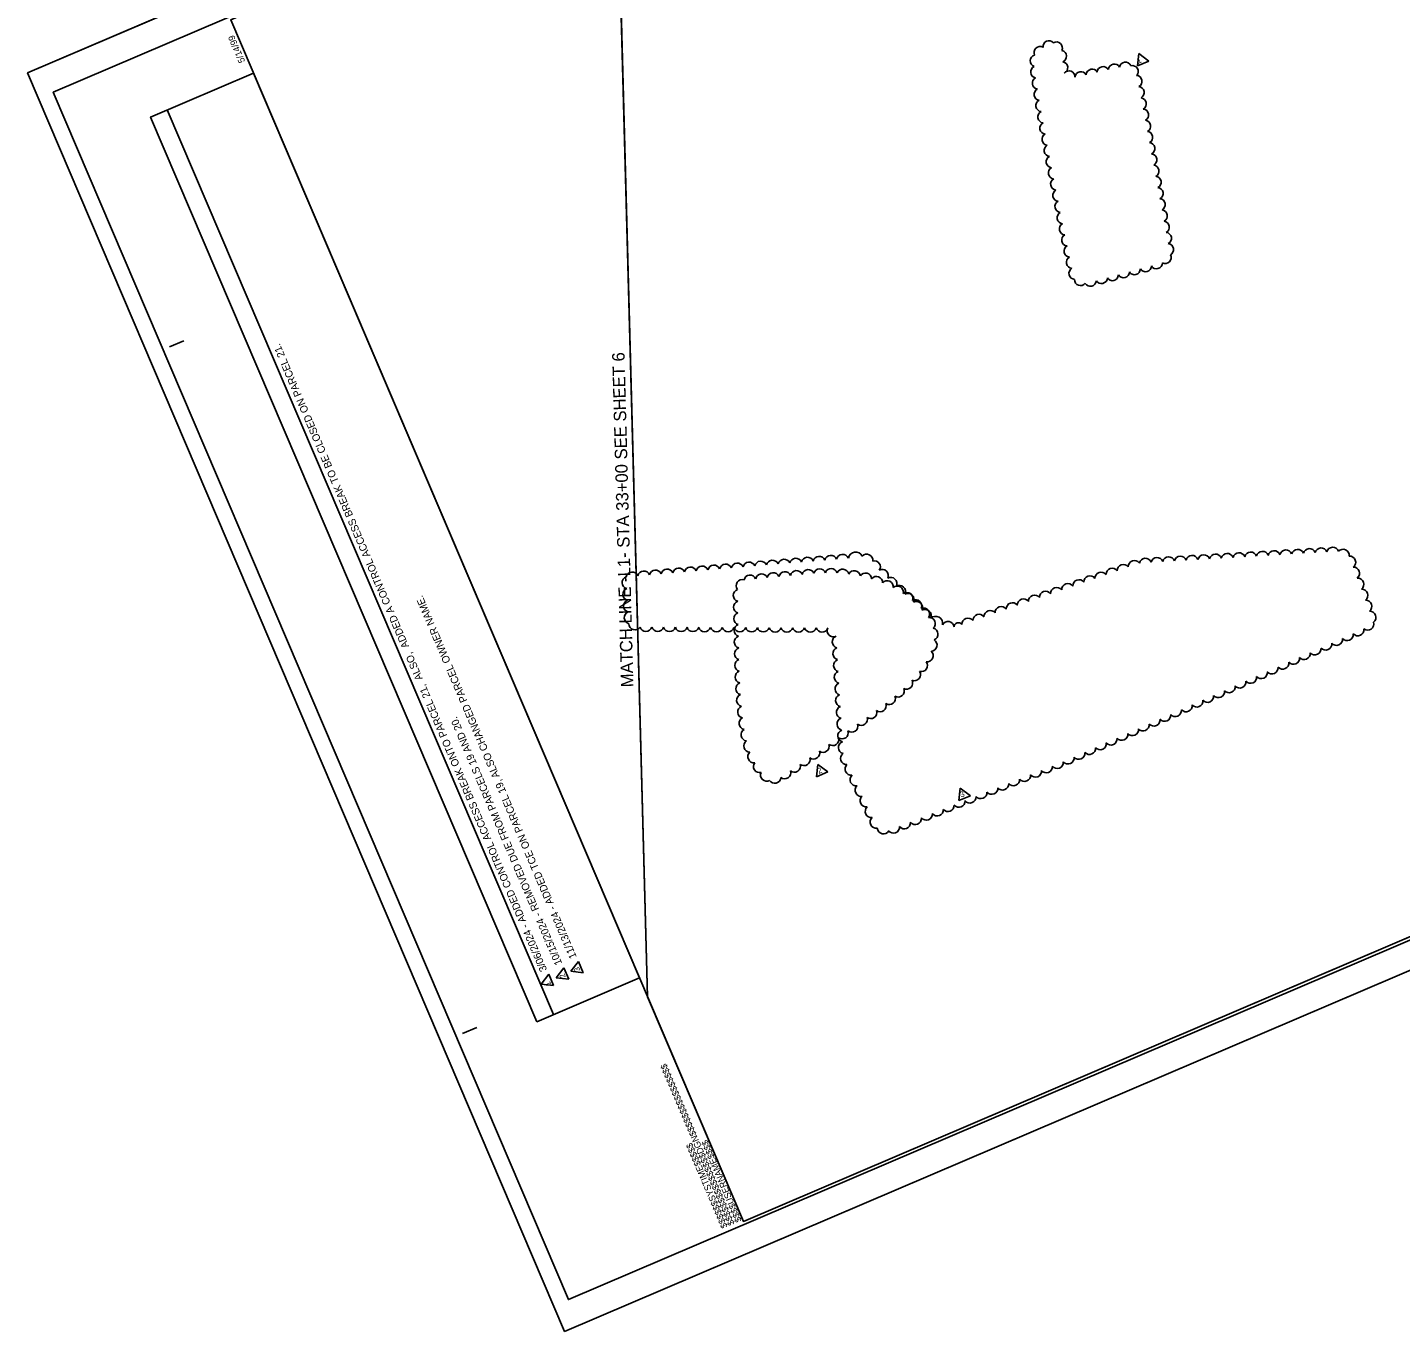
# Model space of a CAD drawing. Extents: x 2192740 to 2194721, y 86011 to 87688.
# Drawn here: x 2192740 to 2193845, y 86011 to 87060 of the extents above; entities that cross this region are included whole.
import ezdxf

# ---------------------------------------------------------------- set-up
doc = ezdxf.new("R2010")
doc.units = 0
for name, color, linetype in [('CTL Primary Horizontal Cogo Comment', 7, 'Continuous'), ('CTL Primary Horizontal Cogo Elevation', 7, 'Continuous'), ('CTL Primary Horizontal Cogo Number', 7, 'Continuous'), ('Exist Other Culture Sign', 7, 'Continuous'), ('Exist Property Iron Pin Cogo Comment', 7, 'Continuous'), ('Exist Utilities Other Traffic Signal Box CELL', 7, 'Continuous'), ('Old_Level_6', 7, 'Continuous')]:
    doc.layers.add(name, color=color, linetype=linetype)

msp = doc.modelspace()

# ---------------------------------------------------------------- linework, layer by layer
at = {"layer": 'CTL Primary Horizontal Cogo Comment'}
for p, q in [((2194289.2, 87684.3), (2192740.5, 87023)), ((2192740.5, 87023), (2193172.4, 86011.4)), ((2193172.4, 86011.4), (2194721.1, 86672.6))]:
    msp.add_line(p, q, dxfattribs=at)
at = {"layer": 'CTL Primary Horizontal Cogo Elevation'}
msp.add_lwpolyline([(2194289.2, 87684.3), (2192740.5, 87023), (2193172.4, 86011.4), (2194721.1, 86672.6)], close=True, dxfattribs=at)
at = {"layer": 'CTL Primary Horizontal Cogo Number'}
msp.add_lwpolyline([(2194293.9, 87661.9), (2192761.2, 87007.5), (2193175.5, 86037.1), (2194708.2, 86691.5)], close=True, dxfattribs=at)
at = {"layer": 'Exist Other Culture Sign'}
for p, q in [((2192854.6, 86802.7), (2192866.1, 86807.6)), ((2193090.2, 86250.8), (2193101.7, 86255.8))]:
    msp.add_line(p, q, dxfattribs=at)
msp.add_lwpolyline([(2194283.4, 87654.6), (2192903.9, 87065.6), (2193316.2, 86099.9), (2194695.7, 86688.9)], close=True, dxfattribs=at)
at = {"layer": 'Exist Property Iron Pin Cogo Comment'}
msp.add_line((2193214.5, 87198.2), (2193239.1, 86280.3), dxfattribs=at)
at = {"layer": 'Exist Utilities Other Traffic Signal Box CELL'}
msp.add_lwpolyline([(2194135.7, 87491), (2194167.5, 87416.4), (2194338.2, 87489.3), (2194682.4, 86683.3), (2193316.2, 86099.9), (2193239.1, 86280.3), (2193214.5, 87198.2), (2193975.8, 87523.3), (2194012.1, 87438.3)], close=True, dxfattribs=at)
at = {"layer": 'Old_Level_6'}
for p, q in [((2193633.1, 87028.6), (2193634.2, 87038.6)), ((2193633.1, 87028.6), (2193642.3, 87032.5)), ((2193634.2, 87038.6), (2193642.3, 87032.5)), ((2193163.4, 86266.1), (2192852.9, 86993.3)), ((2193374.9, 86457.2), (2193376, 86467.2)), ((2193374.9, 86457.2), (2193384, 86461.1)), ((2193376, 86467.2), (2193384, 86461.1)), ((2193489.5, 86438.1), (2193490.6, 86448.2)), ((2193490.6, 86448.2), (2193498.7, 86442)), ((2193489.5, 86438.1), (2193498.7, 86442)), ((2193165.6, 86295.7), (2193171.8, 86303.7)), ((2193175.7, 86294.6), (2193171.8, 86303.7)), ((2193177.4, 86300.9), (2193183.5, 86308.9)), ((2193187.4, 86299.8), (2193183.5, 86308.9)), ((2193153.6, 86290.6), (2193159.7, 86298.6)), ((2193163.6, 86289.5), (2193159.7, 86298.6)), ((2193175.7, 86294.6), (2193165.6, 86295.7)), ((2193187.4, 86299.8), (2193177.4, 86300.9)), ((2193163.6, 86289.5), (2193153.6, 86290.6))]:
    msp.add_line(p, q, dxfattribs=at)
msp.add_lwpolyline([(2193150, 86260.4), (2192839.5, 86987.5), (2192922.1, 87022.8), (2193232.6, 86295.7)], close=True, dxfattribs=at)
for centre, radius, start, end in [((2193554.7, 87039.4), 4.81, 60.2889, 205.2889), ((2193561.9, 87044), 4.81, 41.2058, 186.2058), ((2193567.9, 87043.1), 4.81, 335.2487, 120.2487), ((2193551.6, 87032.7), 4.81, 104.9388, 249.9388), ((2193571.2, 87036.4), 4.81, 291.3424, 76.3424), ((2193572.2, 87027.2), 4.81, 295.7959, 80.7959), ((2193623.4, 87026.8), 4.81, 24.9884, 169.9884), ((2193552, 87023.8), 4.81, 114.7308, 259.7308), ((2193578, 87019.9), 4.81, 357.2597, 142.2597), ((2193587.6, 87019.2), 4.81, 29.5837, 174.5837), ((2193596.6, 87021.2), 4.81, 30.4862, 175.4862), ((2193605.5, 87023.3), 4.81, 30.7446, 175.7446), ((2193614.5, 87025.3), 4.81, 29.3713, 174.3713), ((2193628.9, 87024.1), 4.81, 318.561, 103.561), ((2193631.9, 87016.2), 4.81, 298.7576, 83.7576), ((2193553.3, 87014.7), 4.81, 116.1613, 261.1613), ((2193554.7, 87005.7), 4.81, 116.8755, 261.8755), ((2193633.7, 87007.2), 4.81, 298.4514, 83.4514), ((2193556.2, 86996.7), 4.81, 117.3247, 262.3247), ((2193635.4, 86998.2), 4.81, 298.3036, 83.3036), ((2193557.8, 86987.6), 4.81, 117.6408, 262.6408), ((2193637.2, 86989.2), 4.81, 298.2119, 83.2119), ((2193559.4, 86978.6), 4.81, 117.879, 262.879), ((2193638.9, 86980.2), 4.81, 298.1478, 83.1478), ((2193640.5, 86971.2), 4.81, 298.0998, 83.0998), ((2193561.1, 86969.6), 4.81, 118.0667, 263.0667), ((2193562.8, 86960.6), 4.81, 118.2196, 263.2196), ((2193642.2, 86962.2), 4.81, 298.0621, 83.0621), ((2193564.5, 86951.6), 4.81, 118.3473, 263.3473), ((2193643.9, 86953.1), 4.81, 298.0314, 83.0314), ((2193566.2, 86942.6), 4.81, 118.4504, 263.4504), ((2193645.6, 86944.1), 4.81, 298.0179, 83.0179), ((2193568, 86933.6), 4.81, 118.5162, 263.5162), ((2193647.3, 86935.1), 4.81, 298.0179, 83.0179), ((2193569.8, 86924.6), 4.81, 118.5875, 263.5875), ((2193648.9, 86926.1), 4.81, 298.0179, 83.0179), ((2193650.6, 86917.1), 4.81, 298.0179, 83.0179), ((2193571.5, 86915.6), 4.81, 118.6737, 263.6737), ((2193573.3, 86906.6), 4.81, 118.781, 263.781), ((2193652.3, 86908.1), 4.81, 298.0179, 83.0179), ((2193575.1, 86897.6), 4.81, 118.9194, 263.9194), ((2193653.9, 86899), 4.81, 298.0179, 83.0179), ((2193576.9, 86888.6), 4.81, 119.108, 264.108), ((2193655.6, 86890), 4.81, 298.0179, 83.0179), ((2193578.8, 86879.7), 4.81, 119.3871, 264.3871), ((2193655.3, 86874.5), 4.81, 243.0878, 28.0878), ((2193657.3, 86881), 4.81, 298.0179, 83.0179), ((2193580.7, 86870.7), 4.81, 119.8662, 264.8662), ((2193582.8, 86861.8), 4.81, 121.0572, 266.0572), ((2193630.6, 86865.6), 4.81, 212.7782, 357.7782), ((2193639.5, 86868), 4.81, 212.7782, 357.7782), ((2193648.3, 86870.4), 4.81, 212.7782, 357.7782), ((2193587.2, 86856.8), 4.8, 177.6331, 322.6331), ((2193595.2, 86856.3), 4.81, 210.4677, 355.4677), ((2193604.1, 86858.5), 4.81, 211.7465, 356.7465), ((2193612.9, 86860.8), 4.81, 212.3611, 357.3611), ((2193621.8, 86863.2), 4.81, 212.7195, 357.7195), ((2193367.7, 86628.8), 4.95, 22.3196, 167.3196), ((2193377.1, 86629.5), 4.95, 22.3196, 167.3196), ((2193386.5, 86630.3), 4.95, 22.3196, 167.3196), ((2193396, 86631.1), 4.95, 22.3196, 167.3196), ((2193406.4, 86632), 5.9, 25.3586, 170.3586), ((2193415.3, 86631.2), 4.95, 352.372, 137.372), ((2193648.8, 86628.5), 4.95, 20.8306, 165.8306), ((2193658.2, 86629.1), 4.95, 20.8306, 165.8306), ((2193667.6, 86629.6), 4.95, 20.8306, 165.8306), ((2193677, 86630.2), 4.95, 20.8306, 165.8306), ((2193686.5, 86630.7), 4.95, 20.8306, 165.8306), ((2193695.9, 86631.3), 4.95, 20.8306, 165.8306), ((2193705.3, 86631.8), 4.95, 20.8306, 165.8306), ((2193714.7, 86632.4), 4.95, 20.8306, 165.8306), ((2193724.2, 86632.9), 4.95, 20.8306, 165.8306), ((2193733.6, 86633.5), 4.95, 20.8306, 165.8306), ((2193743, 86634), 4.95, 20.8306, 165.8306), ((2193752.4, 86634.6), 4.95, 20.8306, 165.8306), ((2193761.9, 86635.1), 4.95, 20.8306, 165.8306), ((2193771.3, 86635.7), 4.95, 20.8306, 165.8306), ((2193780.7, 86636.2), 4.95, 20.8306, 165.8306), ((2193790.1, 86636.8), 4.95, 20.8306, 165.8306), ((2193798.4, 86635.2), 4.95, 353.2616, 138.2616), ((2193803.6, 86629.7), 4.95, 307.6704, 92.6704), ((2193236.1, 86617.7), 4.95, 22.3196, 167.3196), ((2193245.5, 86618.4), 4.95, 22.3196, 167.3196), ((2193254.9, 86619.2), 4.95, 22.3196, 167.3196), ((2193264.3, 86620), 4.95, 22.3196, 167.3196), ((2193273.7, 86620.8), 4.95, 22.3196, 167.3196), ((2193283.1, 86621.6), 4.95, 22.3196, 167.3196), ((2193292.5, 86622.4), 4.95, 22.3196, 167.3196), ((2193301.9, 86623.2), 4.95, 22.3196, 167.3196), ((2193311.3, 86624), 4.95, 22.3196, 167.3196), ((2193320.7, 86624.8), 4.95, 22.3196, 167.3196), ((2193330.1, 86625.6), 4.95, 22.3196, 167.3196), ((2193339.5, 86626.4), 4.95, 22.3196, 167.3196), ((2193348.9, 86627.2), 4.95, 22.3196, 167.3196), ((2193349.6, 86617.2), 4.92, 22.9559, 167.9559), ((2193358.3, 86628), 4.95, 22.3196, 167.3196), ((2193358.9, 86618.1), 4.92, 22.9559, 167.9559), ((2193368.3, 86618.9), 4.92, 22.63, 167.63), ((2193377.6, 86619.5), 4.92, 19.9186, 164.9186), ((2193386.8, 86619.7), 4.92, 16.408, 161.408), ((2193396.1, 86619.2), 4.92, 12.4747, 157.4747), ((2193405.3, 86618), 4.92, 8.0943, 153.0943), ((2193421.7, 86626.1), 4.64, 323.0557, 108.0557), ((2193427.8, 86619), 4.95, 334.3989, 119.3989), ((2193612.8, 86619.9), 4.95, 36.5816, 181.5816), ((2193621.7, 86623), 4.95, 36.5816, 181.5816), ((2193630.6, 86626.1), 4.95, 36.5816, 181.5816), ((2193639.4, 86627.9), 4.95, 21.8357, 166.8357), ((2193806.8, 86620.9), 4.95, 307.6704, 92.6704), ((2193223.6, 86613.3), 4.95, 110.9039, 255.9039), ((2193226.7, 86616.9), 4.95, 22.3196, 167.3196), ((2193315.3, 86610.8), 4.92, 73.4623, 218.4623), ((2193321.5, 86614.5), 4.92, 22.9559, 167.9559), ((2193330.9, 86615.4), 4.92, 22.9559, 167.9559), ((2193340.2, 86616.3), 4.92, 22.9559, 167.9559), ((2193414.4, 86616.1), 4.92, 3.2672, 148.2672), ((2193423.2, 86613.4), 4.92, 358.0319, 143.0319), ((2193431.8, 86609.9), 4.92, 352.4751, 137.4751), ((2193434.7, 86612.6), 4.95, 334.3989, 119.3989), ((2193441.6, 86606.1), 4.95, 334.3989, 119.3989), ((2193577.1, 86607.6), 4.95, 36.5816, 181.5816), ((2193586, 86610.7), 4.95, 36.5816, 181.5816), ((2193594.9, 86613.8), 4.95, 36.5816, 181.5816), ((2193603.8, 86616.8), 4.95, 36.5816, 181.5816), ((2193810.1, 86612), 4.95, 307.6704, 92.6704), ((2193224.2, 86603.9), 4.95, 110.9039, 255.9039), ((2193313, 86603.1), 4.92, 108.6436, 253.6436), ((2193439.9, 86605.6), 4.92, 346.7306, 131.7306), ((2193447.6, 86600.5), 4.92, 340.9648, 125.9648), ((2193448.5, 86599.7), 4.95, 334.3989, 119.3989), ((2193541.4, 86595.2), 4.95, 36.5816, 181.5816), ((2193550.3, 86598.3), 4.95, 36.5816, 181.5816), ((2193559.2, 86601.4), 4.95, 36.5816, 181.5816), ((2193568.1, 86604.5), 4.95, 36.5816, 181.5816), ((2193813.4, 86603.1), 4.95, 307.6704, 92.6704), ((2193224.7, 86594.5), 4.95, 110.9039, 255.9039), ((2193225.3, 86585.1), 4.95, 110.9039, 255.9039), ((2193313.2, 86593.7), 4.92, 108.6436, 253.6436), ((2193313.4, 86584.3), 4.92, 108.6436, 253.6436), ((2193454.7, 86594.6), 4.92, 335.3457, 120.3457), ((2193455.4, 86593.2), 4.95, 334.3989, 119.3989), ((2193461, 86588), 4.92, 326.3341, 111.3341), ((2193462.3, 86586.8), 4.95, 334.3989, 119.3989), ((2193514.6, 86586), 4.95, 36.5816, 181.5816), ((2193523.5, 86589.1), 4.95, 36.5816, 181.5816), ((2193532.5, 86592.2), 4.95, 36.5816, 181.5816), ((2193816.6, 86594.3), 4.95, 307.6704, 92.6704), ((2193819.9, 86585.4), 4.95, 307.6704, 92.6704), ((2193229, 86580.3), 4.95, 180.9397, 325.9397), ((2193313.6, 86574.9), 4.92, 108.6436, 253.6436), ((2193465.6, 86580.4), 4.92, 310.696, 95.696), ((2193470.7, 86580.5), 5.75, 348.6707, 133.6707), ((2193480.7, 86577.1), 4.95, 7.6494, 152.6494), ((2193489, 86577.7), 3.4, 34.7452, 179.7452), ((2193496.8, 86579.8), 4.95, 36.5816, 181.5816), ((2193505.7, 86582.9), 4.95, 36.5816, 181.5816), ((2193818.2, 86580), 4.95, 233.1088, 18.1088), ((2193237.8, 86579), 4.95, 197.2284, 342.2284), ((2193247.3, 86579), 4.95, 197.2284, 342.2284), ((2193256.7, 86578.9), 4.95, 197.2284, 342.2284), ((2193266.2, 86578.9), 4.95, 197.2284, 342.2284), ((2193275.6, 86578.9), 4.95, 197.2284, 342.2284), ((2193285, 86578.8), 4.95, 197.2284, 342.2284), ((2193294.5, 86578.8), 4.95, 197.2284, 342.2284), ((2193303.9, 86578.7), 4.95, 197.2284, 342.2284), ((2193313.4, 86578.7), 4.95, 197.2284, 342.2284), ((2193313.8, 86565.5), 4.92, 108.6436, 253.6436), ((2193322.8, 86578.6), 4.95, 197.2284, 342.2284), ((2193332.2, 86578.6), 4.95, 197.2284, 342.2284), ((2193341.7, 86578.5), 4.95, 197.2284, 342.2284), ((2193351.1, 86578.5), 4.95, 197.2284, 342.2284), ((2193360.5, 86578.5), 4.95, 197.2284, 342.2284), ((2193370, 86578.4), 4.95, 197.2284, 342.2284), ((2193379.4, 86578.4), 4.95, 197.2284, 342.2284), ((2193388.5, 86574.6), 4.95, 152.7428, 297.7428), ((2193392.6, 86565.6), 4.95, 110.8294, 255.8294), ((2193467, 86563.1), 4.92, 274.1817, 59.1817), ((2193467.7, 86571.9), 4.92, 291.6398, 76.6398), ((2193793, 86567.8), 4.95, 221.348, 6.348), ((2193801.7, 86571.6), 4.95, 221.348, 6.348), ((2193810.3, 86575.5), 4.95, 221.348, 6.348), ((2193314, 86556.2), 4.92, 108.6436, 253.6436), ((2193393.1, 86556.2), 4.95, 110.8294, 255.8294), ((2193463.9, 86554.6), 4.92, 261.4411, 46.4411), ((2193767.1, 86556.4), 4.95, 221.348, 6.348), ((2193775.8, 86560.2), 4.95, 221.348, 6.348), ((2193784.4, 86564), 4.95, 221.348, 6.348), ((2193314.2, 86546.8), 4.92, 109.0095, 254.0095), ((2193393.7, 86546.7), 4.95, 110.8294, 255.8294), ((2193459.3, 86546.7), 4.92, 252.7888, 37.7888), ((2193741.2, 86544.9), 4.95, 221.348, 6.348), ((2193749.9, 86548.7), 4.95, 221.348, 6.348), ((2193758.5, 86552.6), 4.95, 221.348, 6.348), ((2193314.5, 86537.4), 4.92, 109.8306, 254.8306), ((2193394.2, 86537.3), 4.95, 110.8294, 255.8294), ((2193447.4, 86532.6), 4.92, 242.4529, 27.4529), ((2193453.7, 86539.4), 4.92, 246.7935, 31.7935), ((2193715.3, 86533.5), 4.95, 221.348, 6.348), ((2193724, 86537.3), 4.95, 221.348, 6.348), ((2193732.6, 86541.1), 4.95, 221.348, 6.348), ((2193315, 86528.1), 4.92, 110.8202, 255.8202), ((2193315.6, 86518.7), 4.92, 112.0442, 257.0442), ((2193394.8, 86527.9), 4.95, 110.8294, 255.8294), ((2193395.3, 86518.5), 4.95, 110.8294, 255.8294), ((2193440.6, 86526.2), 4.92, 239.1737, 24.1737), ((2193698.1, 86525.8), 4.95, 221.348, 6.348), ((2193706.7, 86529.7), 4.95, 221.348, 6.348), ((2193316.5, 86509.4), 4.92, 113.6099, 258.6099), ((2193395.9, 86509), 4.95, 110.8294, 255.8294), ((2193426.1, 86514.4), 4.92, 234.5359, 19.5359), ((2193433.5, 86520.2), 4.92, 236.6059, 21.6059), ((2193672.2, 86514.4), 4.95, 221.348, 6.348), ((2193680.8, 86518.2), 4.95, 221.348, 6.348), ((2193689.4, 86522), 4.95, 221.348, 6.348), ((2193317.6, 86500.2), 4.92, 115.708, 260.708), ((2193396.4, 86499.6), 4.95, 110.8294, 255.8294), ((2193411, 86503.5), 4.92, 232.842, 17.842), ((2193418.6, 86508.9), 4.92, 233.0507, 18.0507), ((2193646.3, 86502.9), 4.95, 221.348, 6.348), ((2193654.9, 86506.8), 4.95, 221.348, 6.348), ((2193663.5, 86510.6), 4.95, 221.348, 6.348), ((2193319.2, 86491), 4.92, 118.7153, 263.7153), ((2193397, 86490.2), 4.95, 110.8294, 255.8294), ((2193395.6, 86492.6), 4.92, 232.7115, 17.7115), ((2193403.3, 86498), 4.92, 232.7828, 17.7828), ((2193620.4, 86491.5), 4.95, 221.348, 6.348), ((2193629, 86495.3), 4.95, 221.348, 6.348), ((2193637.6, 86499.1), 4.95, 221.348, 6.348), ((2193321.4, 86482), 4.92, 123.5083, 268.5083), ((2193380.3, 86481.8), 4.92, 232.5108, 17.5108), ((2193388, 86487.2), 4.92, 232.6235, 17.6235), ((2193397.5, 86480.8), 4.95, 110.8294, 255.8294), ((2193594.5, 86480.1), 4.95, 221.348, 6.348), ((2193603.1, 86483.9), 4.95, 221.348, 6.348), ((2193611.7, 86487.7), 4.95, 221.348, 6.348), ((2193324.6, 86473.4), 4.92, 132.5977, 277.5977), ((2193329.1, 86465.5), 4.92, 141.2417, 286.2417), ((2193364.9, 86471.1), 4.92, 232.1395, 17.1395), ((2193372.6, 86476.4), 4.92, 232.3593, 17.3593), ((2193399.3, 86472), 4.95, 126.9793, 271.9793), ((2193568.5, 86468.9), 4.95, 219.05, 4.05), ((2193577.2, 86472.5), 4.95, 220.9183, 5.9183), ((2193585.8, 86476.2), 4.95, 221.348, 6.348), ((2193334.9, 86458.6), 4.92, 153.5317, 298.5317), ((2193341.3, 86456.9), 4.92, 212.9277, 357.9277), ((2193349.4, 86460.6), 4.92, 230.976, 15.976), ((2193357.1, 86465.8), 4.92, 231.7769, 16.7769), ((2193402.8, 86463.5), 4.95, 132.9614, 277.9614), ((2193406.9, 86454.9), 4.95, 132.9614, 277.9614), ((2193542.2, 86458.5), 4.95, 219.05, 4.05), ((2193551, 86461.9), 4.95, 219.05, 4.05), ((2193559.7, 86465.4), 4.95, 219.05, 4.05), ((2193411, 86446.4), 4.95, 132.9614, 277.9614), ((2193515.9, 86448.1), 4.95, 219.05, 4.05), ((2193524.6, 86451.5), 4.95, 219.05, 4.05), ((2193533.4, 86455), 4.95, 219.05, 4.05), ((2193415, 86437.9), 4.95, 132.9614, 277.9614), ((2193480.7, 86434.2), 4.95, 219.05, 4.05), ((2193489.5, 86437.7), 4.95, 219.05, 4.05), ((2193498.3, 86441.1), 4.95, 219.05, 4.05), ((2193507.1, 86444.6), 4.95, 219.05, 4.05), ((2193419.1, 86429.4), 4.95, 132.9614, 277.9614), ((2193423.1, 86420.8), 4.95, 132.9614, 277.9614), ((2193454.4, 86423.8), 4.95, 219.05, 4.05), ((2193463.2, 86427.3), 4.95, 219.05, 4.05), ((2193472, 86430.7), 4.95, 219.05, 4.05), ((2193428.8, 86416.3), 4.95, 184.0171, 329.0171), ((2193436.8, 86416.9), 4.95, 219.05, 4.05), ((2193445.6, 86420.3), 4.95, 219.05, 4.05)]:
    msp.add_arc(centre, radius, start, end, dxfattribs=at)

# ---------------------------------------------------------------- texts
at = {"layer": 'Exist Other Culture Sign'}
for s, p in [('5/14/99', (2192915.6, 87032.3)), ('$$$$$$$$$$$$$$$$DGN$$$$$$$$$$$$$$$$', (2193309.2, 86097.9)), ('$$$$$$SYSTIME$$$$$', (2193303.6, 86095.7)), ('$$$$USERNAME$$$$', (2193315, 86100.5))]:
    msp.add_text(s, height=5.25, rotation=113.1206, dxfattribs=at).set_placement(p)
at = {"layer": 'Exist Property Iron Pin Cogo Comment'}
msp.add_text('MATCH LINE -L1- STA 33+00 SEE SHEET 6', height=10, rotation=91.5395, dxfattribs=at).set_placement((2193227.8, 86529.3))
at = {"layer": 'Old_Level_6'}
for s, height, rotation, p in [(' 1', 4.5, 23.1206, (2193632.2, 87029.7)), ('  3/06/2024 - ADDED CONTROL ACCESS BREAK ONTO PARCEL 21,  ALSO,  ADDED A CONTROL ACCESS BREAK TO BE CLOSED ON PARCEL 21.', 6, 113.1206, (2193160.2, 86298)), ('  11/13/2024 - ADDED TCE ON PARCEL 19, ALSO CHANGED PARCEL OWNER NAME.', 6, 113.1206, (2193184, 86308.4)), ('  10/15/2024 - REMOVED DUE FROM PARCELS 19 AND 20.', 6, 113.1206, (2193172.3, 86303.2)), ('2', 4.5, 23.1206, (2193376.8, 86459.5)), ('3', 4.5, 23.1206, (2193491.5, 86440.5)), ('3', 4.5, 113.1206, (2193185.1, 86301.7)), (' 1', 4.5, 113.1206, (2193162.5, 86288.6)), ('2', 4.5, 113.1206, (2193173.4, 86296.5))]:
    msp.add_text(s, height=height, rotation=rotation, dxfattribs=at).set_placement(p)

doc.saveas('drawing.dxf')
